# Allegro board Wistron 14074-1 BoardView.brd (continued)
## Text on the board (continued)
User.32: Anti pad to Anti pad Check,Jul 21 13:44:05 2014,51 errors | BGA From Routing Tab Check,Jul 21 16:29:59 2014,Passed | Board Accuracy Check,Mar 28 09:46:58 2015,Passed | Capacitor Orrientation Check,Jul 21 16:29:59 2014,Passed | Comp From Routing Tab Check,Jul 21 16:30:07 2014,Passed | Comp Pad To Comp Pad Check,Jul 21 16:30:05 2014,31 errors | Component On Edge Check,Jul 21 16:30:05 2014,53 errors | Component Overlap Check,Jul 21 16:30:01 2014,21 errors | Component[Pitch] On Edge Check,Jul 21 16:30:07 2014,Passed | Cross Moat Check,Jul 21 13:44:06 2014,290 errors | DIMM 10mm Area Check,Jul 21 16:30:07 2014,Passed | Dummy-Static-No Shape On Layer Check,Mar 28 09:46:58 2015,1 errors | GF Inner Layer Shape Check,Jul 21 13:44:11 2014,Warning | Height Limit Check,Jul 21 16:30:07 2014,25 errors | Hole Clearance Check,Jul 21 13:44:11 2014,31 errors | Inner Layer for Holes Check,Jul 21 13:44:22 2014,14 errors | Inner Trace Clearance Check,Jul 21 13:44:11 2014,Passed | LF HASL Via Check,Jul 23 16:44:07 2014,2239 errors | Library Path Check,Jul 21 16:30:07 2014,3 errors | Markin Check,Jul 21 16:30:07 2014,1 errors | Markout And Tooling Hole Check,Jul 21 16:30:07 2014,Warning | NPTH Clearance Check,Jul 21 13:44:11 2014,Passed | Outline Clearance Check,Jul 21 13:44:11 2014,Passed | Placement Balance Check,Jul 21 16:30:07 2014,Warning | Power Exit On Two Pins Check,Jul 21 13:44:15 2014,292 errors | Proper Pad Entry Check,Jul 21 13:44:15 2014,1314 errors | Shape Apperture Check,Jul 21 13:44:09 2014,496 errors | Small Comp Near Big Comp Check,Jul 21 16:30:08 2014,11 errors | Split Plane Check,Mar 28 09:46:57 2015,1 errors | Thru Pin To SMD Clearance Check,Jul 21 16:30:07 2014,18 errors | Trace To Trace Spacing Check,Jul 21 13:44:22 2014,378 errors | Via Aspect Ratio Check,Jul 23 16:44:10 2014,7 errors | Via Check,Jul 23 16:44:12 2014,53 errors | Via Connectivity,Jul 23 16:44:12 2014,93 errors | Via On Moat Check,Jul 23 16:44:08 2014,56 errors | Via On Pad Check,Jul 23 16:44:07 2014,47 errors | Via To Via Per Net Check,Jul 23 16:44:10 2014,Warning | Via To Via Spacing Check,Jul 23 16:44:10 2014,2091 errors | Via Type Check,Jul 23 16:44:10 2014,47 errors
User.37: 1 | 204 | OSC1:48MHZ | X2101:25MHZ | X3502:32.768KHZ | 14044-SA | 48.N0077.0SA | A | B | Brian | MADE IN TAIWAN
User.39: ByImpedance:100.0@_REF_L1=("4.0/12.0(L1)")|Type="DP"|_REF_L4=("4.0/12.0(L4)")|_REF_L3=("nil(L3)")|imp="100.0" | ByImpedance:32.0@_REF_L1=("9.5(L1)")|Type="SE"|_REF_L4=("9.5(L4)")|_REF_L3=("9.0(L3)")|imp="32.0" | ByImpedance:34.0@_REF_L1=("9.0(L1)")|Type="SE"|_REF_L4=("9.0(L4)")|_REF_L3=("8.0(L3)")|imp="34.0" | ByImpedance:35.0@_REF_L1=("8.5(L1)")|Type="SE"|_REF_L4=("8.5(L4)")|_REF_L3=("7.5(L3)")|imp="35.0" | ByImpedance:37.5@_REF_L1=("7.5(L1)")|Type="SE"|_REF_L4=("7.5(L4)")|_REF_L3=("7.0(L3)")|imp="37.5" | ByImpedance:39.0@_REF_L1=("7.0(L1)")|Type="SE"|_REF_L4=("7.0(L4)")|_REF_L3=("6.5(L3)")|imp="39.0" | ByImpedance:40.0@_REF_L1=("6.5(L1)")|Type="SE"|_REF_L4=("6.5(L4)")|_REF_L3=("6.0(L3)")|imp="40.0" | ByImpedance:42.0@_REF_L1=("6.0(L1)")|Type="SE"|_REF_L4=("6.0(L4)")|_REF_L3=("5.5(L3)")|imp="42.0" | ByImpedance:45.0@_REF_L1=("5.0(L1)")|Type="SE"|_REF_L4=("5.0(L4)")|_REF_L3=("4.5(L3)")|imp="45.0" | ByImpedance:50.0@_REF_L1=("4.0(L1)")|Type="SE"|_REF_L4=("4.0(L4)")|_REF_L3=("4.0(L3)")|imp="50.0" | ByImpedance:62.0@_REF_L1=("8.5/5.0(L1)")|Type="DP"|_REF_L4=("8.5/5.0(L4)")|_REF_L3=("7.5/5.0(L3)")|imp="62.0" | ByImpedance:65.0@_REF_L1=("8.0/5.0(L1)")|Type="DP"|_REF_L4=("8.0/5.0(L4)")|_REF_L3=("7.0/5.5(L3)")|imp="65.0" | ByImpedance:70.0@_REF_L1=("7.0/5.0(L1)")|Type="DP"|_REF_L4=("7.0/5.0(L4)")|_REF_L3=("6.0/5.0(L3)")|imp="70.0" | ByImpedance:72.0@_REF_L1=("7.0/7.0(L1)")|Type="DP"|_REF_L4=("7.0/7.0(L4)")|_REF_L3=("5.5/5.0(L3)")|imp="72.0" | ByImpedance:80.0@_REF_L1=("6.0/9.0(L1)" "5.0/5.0(L1)")|Type="DP"|_REF_L4=("6.0/9.0(L4)" "5.0/5.0(L4)")|_REF_L3=("4.5/6.0(L3)")|imp="80.0" | ByImpedance:85.0@_REF_L1=("4.0/4.5(L1)" "5.0/7.0(L1)")|Type="DP"|_REF_L4=("4.0/4.5(L4)" "5.0/7.0(L4)")|_REF_L3=("4.0/6.0(L3)")|imp="85.0" | ByImpedance:90.0@_REF_L1=("4.0/6.0(L1)")|Type="DP"|_REF_L4=("4.0/6.0(L4)")|_REF_L3=("4.0/9.0(L3)")|imp="90.0" | ByImpedance:95.0@_REF_L1=("4.0/8.0(L1)")|Type="DP"|_REF_L4=("4.0/8.0(L4)")|_REF_L3=("nil(L3)")|imp="95.0" | LayerIndex:nil | Source:4-1.6-8d.xls | artWorks:("_REF_L3" "_REF_L4" "_REF_L1") | gtImpOutlineUsed:BOARD GEOMETRY/OUTLINE
User.42: This gerber is just for your reference to find the DP impedance traces in layer L1. | DP IMPEDANCE TABLE: L1 | * - Denotes that WIDTH | is NOT used in this layer | inside board outline. | IMP(Ohm) | 62.0 | 65.0 | 70.0 | 72.0 | 80.0 | 85.0 | 90.0 | 95.0 | 100.0 | WIDTH(mils) | *8.5/5.0 | *8.0/5.0 | *7.0/5.0 | *7.0/7.0 | *6.0/9.0 | *5.0/5.0 | 4.0/4.5 | *5.0/7.0 | 4.0/6.0 | *4.0/8.0 | *4.0/12.0 | TYPE | DP
User.44: This gerber is just for your reference to find the SE impedance traces in layer L1. | SE IMPEDANCE TABLE: L1 | * - Denotes that WIDTH | is NOT used in this layer | inside board outline. | IMP(Ohm) | 32.0 | 34.0 | 35.0 | 37.5 | 39.0 | 40.0 | 42.0 | 45.0 | 50.0 | WIDTH(mils) | *9.5 | *9.0 | *8.5 | *7.5 | 7.0 | 6.5 | 6.0 | *5.0 | 4.0 | TYPE | SE
User.45: This gerber is just for you reference to find the differential traces in layer BOTTOM | This gerber is just for you reference to find the differential traces in layer L3 | This gerber is just for you reference to find the differential traces in layer TOP | Note:Refer to DRILL layer for ELLIPSE drill direction | FIGURE | SIZE | 8.0 | 10.0 | 12.0 | 16.0 | 20.0 | 28.0 | 30.0 | 32.0 | 35.0 | 36.0 | 37.0 | 39.0 | 40.0 | 41.0 | 45.0 | 52.0 | 54.0 | 55.0 | 56.0 | 91.0 | 109.0 | 120.0 | 44.0 | 46.0 | 63.0 | 65.0 | 93.0 | 95.0 | 119.0 | 158.0 | 79.0x40.0 | 83.0x36.0 | 91.0x40.0 | 107.0x36.0 | DRILL CHART: TOP to BOTTOM | ALL UNITS ARE IN MILS | PLATED | NON-PLATED | QTY | 505 | 2510 | 59 | 610 | 32 | 164 | 14 | 19 | 13 | 16 | 26 | 66 | 60 | 15 | 4 | 2 | 20 | 24 | 1 | 3 | This gerber is just for your reference to find the DP impedance traces in layer L3. | This gerber is just for your reference to find the DP impedance traces in layer L4. | This gerber is just for your reference to find the SE impedance traces in layer L3. | This gerber is just for your reference to find the SE impedance traces in layer L4. | DP IMPEDANCE TABLE: L3 | DP IMPEDANCE TABLE: L4 | SE IMPEDANCE TABLE: L3 | SE IMPEDANCE TABLE: L4 | * - Denotes that WIDTH | is NOT used in this layer | inside board outline. | Model | DIBSWL-aBrian 4L MB | PCB_NO | 14074 | VER. | Layer | DRILL | L1 | L2VCC | TMASK | TPLACE | TSILK | TSMD | Designer | WENDY | Date | 03/28/2015 | IMP(Ohm) | 62.0 | 34.0 | 70.0 | 37.5 | 72.0 | 80.0 | 85.0 | 42.0 | 90.0 | 100.0 | 50.0 | WIDTH(mils) | *9.0 | *9.5 | *7.5 | *8.5 | *7.0 | *6.5 | 7.0 | 6.0 | *5.5 | *4.5 | 5.0 | 4.0 | *7.5/5.0 | *7.0/5.5 | *6.0/5.0 | *5.5/5.0 | *4.5/6.0 | 4.0/6.0 | *4.0/9.0 | *nil | *8.5/5.0 | *8.0/5.0 | *7.0/5.0 | *7.0/7.0 | *6.0/9.0 | *5.0/5.0 | 4.0/4.5 | *5.0/7.0 | *4.0/8.0 | *4.0/12.0 | TYPE | SE | DP | BMASK | BPLACE | BSILK | BSMD | L3 | L4
